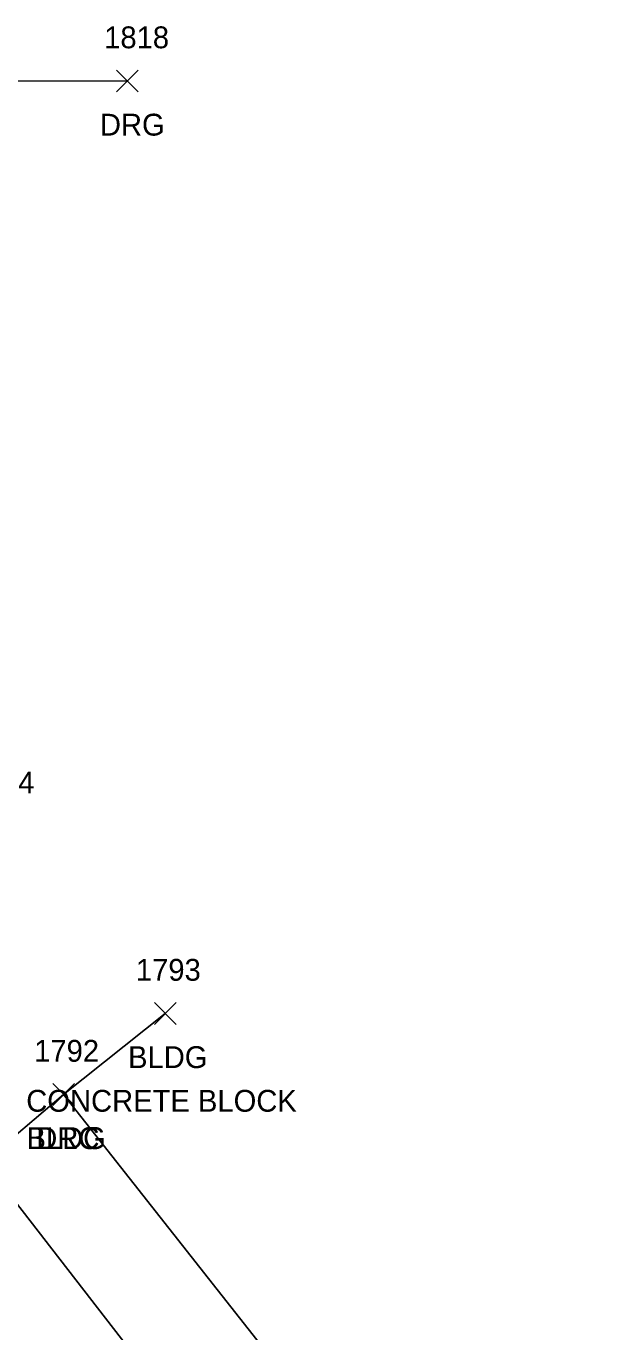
# Model space of a CAD drawing. Extents: x 1653908 to 1654393, y 539913 to 544256.
# Drawn here: x 1654199.7 to 1654253, y 541548 to 541667.7 of the extents above; entities that cross this region are included whole.
import ezdxf

# ---------------------------------------------------------------- set-up
doc = ezdxf.new("R2010")
doc.units = 0
for name, color, linetype in [('L_A', 7, 'Continuous'), ('L_C', 7, 'Continuous'), ('L_I', 7, 'Continuous'), ('L_TIC', 7, 'Continuous'), ('LBC', 7, 'Continuous'), ('R_A', 7, 'Continuous'), ('R_I', 7, 'Continuous'), ('R_TIC', 7, 'Continuous'), ('RDG', 7, 'Continuous'), ('RDP', 7, 'Continuous')]:
    doc.layers.add(name, color=color, linetype=linetype)

msp = doc.modelspace()

# ---------------------------------------------------------------- linework, layer by layer
at = {"layer": 'L_TIC'}
for points in [[(1654211.42, 541576.2), (1654213.42, 541578.2)], [(1654213.42, 541576.2), (1654211.42, 541578.2)], [(1654202.1, 541568.78), (1654204.1, 541570.78)], [(1654204.1, 541568.78), (1654202.1, 541570.78)]]:
    msp.add_lwpolyline(points, dxfattribs=at)
at = {"layer": 'LBC'}
msp.add_lwpolyline([(1654253.02, 541506.18), (1654231.73, 541533.48), (1654203.1, 541569.78), (1654212.42, 541577.2)], dxfattribs=at)
at = {"layer": 'R_TIC'}
for points in [[(1654207.95, 541661.63), (1654209.95, 541663.63)], [(1654209.95, 541661.63), (1654207.95, 541663.63)], [(1654202.1, 541568.78), (1654204.1, 541570.78)], [(1654204.1, 541568.78), (1654202.1, 541570.78)]]:
    msp.add_lwpolyline(points, dxfattribs=at)
at = {"layer": 'RDG'}
msp.add_lwpolyline([(1654146.11, 541619.61), (1654156.56, 541622.67), (1654165.11, 541628.88), (1654170.72, 541637.96), (1654173.41, 541648.79), (1654172.34, 541662.67), (1654208.95, 541662.63)], dxfattribs=at)
at = {"layer": 'RDP'}
msp.add_lwpolyline([(1654244.38, 541502.13), (1654222.95, 541528.61), (1654195.82, 541563.61), (1654203.1, 541569.78)], dxfattribs=at)

# ---------------------------------------------------------------- texts
at = {"layer": 'L_A'}
for p in [(1654209.01, 541572.2), (1654199.69, 541564.78)]:
    msp.add_text('BLDG', height=2, dxfattribs=at).set_placement(p)
at = {"layer": 'L_C'}
msp.add_text('CONCRETE BLOCK', height=2, dxfattribs=at).set_placement((1654199.67, 541568.2))
at = {"layer": 'L_I'}
for s, p in [('1794', (1654194.47, 541597.36)), ('1793', (1654209.73, 541580.2)), ('1792', (1654200.4, 541572.78))]:
    msp.add_text(s, height=2, dxfattribs=at).set_placement(p)
at = {"layer": 'R_A'}
for s, p in [('DRG', (1654206.43, 541657.63)), ('DRC', (1654200.59, 541564.78))]:
    msp.add_text(s, height=2, dxfattribs=at).set_placement(p)
at = {"layer": 'R_I'}
for s, p in [('1818', (1654206.82, 541665.63)), ('1792', (1654200.4, 541572.78))]:
    msp.add_text(s, height=2, dxfattribs=at).set_placement(p)

doc.saveas('drawing.dxf')
